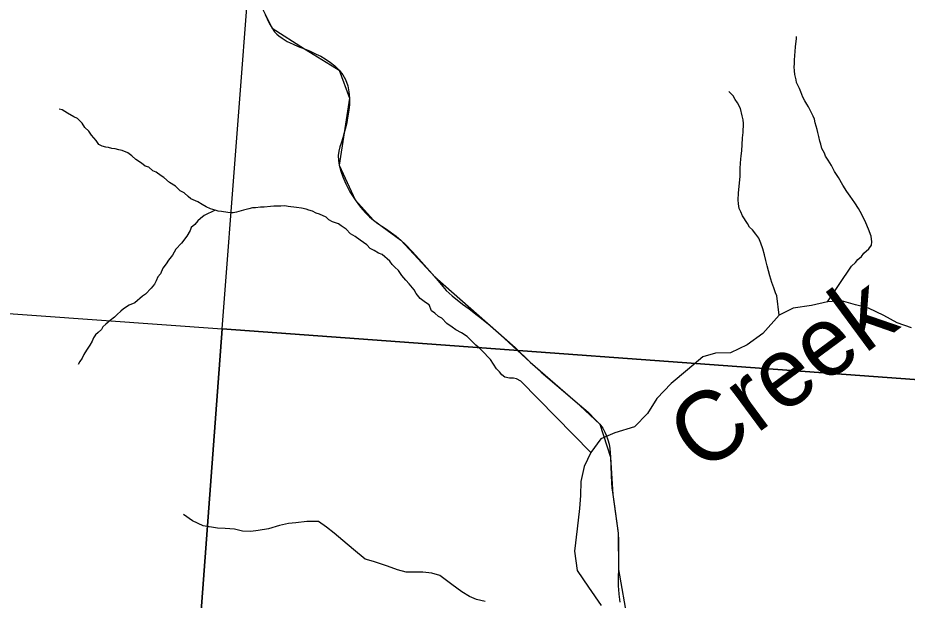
# Model space of a CAD drawing. Extents: x 0 to 82.7, y -0.2 to 22.
# Drawn here: x 6.574 to 7.785, y 18.905 to 19.698 of the extents above; entities that cross this region are included whole.
import ezdxf

# ---------------------------------------------------------------- set-up
doc = ezdxf.new("R2010")
doc.units = 0
for name, color, linetype in [('GM_X_Minor_River', 7, 'Continuous'), ('GM_X_Minor_River_Text', 7, 'Continuous'), ('GM_X_Section', 7, 'Continuous'), ('GM_X_State_Route', 7, 'Continuous'), ('SH_Text', 7, 'Continuous')]:
    doc.layers.add(name, color=color, linetype=linetype)

msp = doc.modelspace()

# ---------------------------------------------------------------- linework, layer by layer
at = {"layer": 'GM_X_Minor_River'}
for points in [[(7.6768, 19.3115), (7.7094, 19.3603), (7.7148, 19.3651), (7.7183, 19.3693), (7.7229, 19.3734), (7.7263, 19.3779), (7.7332, 19.3839), (7.7367, 19.3888), (7.7371, 19.3933), (7.7361, 19.401), (7.7328, 19.4105), (7.7291, 19.4193), (7.7235, 19.4304), (7.7191, 19.4388), (7.7142, 19.4465), (7.7079, 19.4556), (7.703, 19.4618), (7.6978, 19.4702), (7.6918, 19.4806), (7.6862, 19.489), (7.6822, 19.497), (7.6777, 19.5043), (7.6743, 19.51), (7.6725, 19.5139), (7.6692, 19.5204), (7.6677, 19.5261), (7.6662, 19.5303), (7.6652, 19.5364), (7.6637, 19.5421), (7.6626, 19.5459), (7.6615, 19.5508), (7.6601, 19.5554), (7.659, 19.56), (7.6575, 19.5642), (7.6557, 19.568), (7.6508, 19.5768), (7.6486, 19.5807), (7.646, 19.5852), (7.643, 19.5902), (7.6405, 19.5975), (7.6386, 19.6017), (7.6345, 19.6101), (7.6342, 19.6139), (7.6324, 19.6208), (7.6317, 19.6261), (7.6314, 19.6314), (7.6318, 19.6356), (7.6318, 19.6405), (7.6323, 19.6466), (7.6327, 19.6523), (7.6332, 19.6587), (7.6336, 19.6629), (7.6345, 19.6694), (7.6347, 19.6728)], [(7.6111, 19.2933), (7.6077, 19.3197), (7.6058, 19.3236), (7.6036, 19.3308), (7.601, 19.3381), (7.5985, 19.3468), (7.5963, 19.3537), (7.5945, 19.3606), (7.5927, 19.3678), (7.5908, 19.3754), (7.5887, 19.3838), (7.5861, 19.3915), (7.5831, 19.398), (7.5794, 19.4037), (7.5749, 19.4095), (7.5704, 19.4133), (7.5678, 19.4183), (7.5611, 19.4286), (7.5589, 19.434), (7.5567, 19.4386), (7.5556, 19.445), (7.5553, 19.4504), (7.5558, 19.4595), (7.5566, 19.469), (7.5579, 19.4822), (7.5581, 19.4933), (7.5586, 19.5062), (7.5594, 19.51), (7.5602, 19.5176), (7.5607, 19.5251), (7.5612, 19.5346), (7.562, 19.5422), (7.5622, 19.5544), (7.5619, 19.5593), (7.5608, 19.5647), (7.5582, 19.5746), (7.5542, 19.5822), (7.5512, 19.5868), (7.5482, 19.5918), (7.5424, 19.5977)], [(6.7809, 19.4742), (6.773, 19.4807), (6.7692, 19.4831), (6.7624, 19.4881), (6.7583, 19.49), (6.7526, 19.4947), (6.7477, 19.4963), (6.7425, 19.5001), (6.7349, 19.5055), (6.7297, 19.5102), (6.724, 19.5144), (6.7161, 19.5176), (6.7116, 19.5184), (6.7066, 19.5196), (6.7021, 19.5204), (6.6979, 19.5216), (6.6941, 19.522), (6.6889, 19.5236), (6.6847, 19.5259), (6.681, 19.5313), (6.6746, 19.5382), (6.6709, 19.544), (6.6656, 19.549), (6.6619, 19.5547), (6.6555, 19.5609), (6.6506, 19.5632), (6.6419, 19.5683), (6.6348, 19.5729), (6.6306, 19.574)], [(7.3546, 19.1066), (7.2592, 19.2037), (7.2535, 19.2068), (7.2494, 19.2076), (7.2437, 19.2077), (7.2376, 19.2089), (7.2335, 19.212), (7.2301, 19.2162), (7.226, 19.2204), (7.2178, 19.2331), (7.2144, 19.2369), (7.2095, 19.2416), (7.2024, 19.2489), (7.1979, 19.2527), (7.1927, 19.2581), (7.1863, 19.2643), (7.1784, 19.2693), (7.1708, 19.2736), (7.1659, 19.2771), (7.1584, 19.2821), (7.1517, 19.2894), (7.1471, 19.2914), (7.1423, 19.296), (7.1377, 19.2995), (7.1344, 19.3075), (7.1295, 19.3106), (7.122, 19.316), (7.1168, 19.3229), (7.1138, 19.3279), (7.107, 19.3359), (7.1026, 19.3409), (7.0973, 19.3475), (7.0925, 19.354), (7.0876, 19.3586), (7.0842, 19.3624), (7.0808, 19.3667), (7.0703, 19.3759), (7.0654, 19.3779), (7.0594, 19.3814), (7.0541, 19.3841), (7.0496, 19.3891), (7.0406, 19.3953), (7.0334, 19.4007), (7.0274, 19.4042), (7.0214, 19.4104), (7.0146, 19.415), (7.0109, 19.4177), (7.0067, 19.4193), (7.0026, 19.4205), (6.9977, 19.4232), (6.9939, 19.4267), (6.9852, 19.431), (6.9807, 19.4321), (6.9754, 19.4349), (6.9705, 19.4361), (6.9667, 19.4376), (6.9603, 19.4392), (6.9535, 19.4401), (6.9425, 19.4414), (6.9379, 19.4422), (6.9326, 19.4419), (6.9288, 19.4419), (6.9227, 19.4416), (6.9182, 19.4413), (6.9098, 19.4403), (6.9045, 19.4403), (6.8981, 19.4396), (6.8939, 19.4393), (6.8889, 19.4382), (6.8817, 19.4361), (6.8722, 19.4335), (6.8676, 19.4328), (6.8638, 19.4329), (6.8601, 19.4333), (6.8517, 19.4345), (6.8472, 19.435), (6.843, 19.4365), (6.8366, 19.4381), (6.8309, 19.4409), (6.8253, 19.444), (6.8192, 19.4475), (6.8098, 19.4518), (6.806, 19.4549), (6.8008, 19.4599), (6.7955, 19.4626), (6.7888, 19.4688), (6.7809, 19.4742)], [(6.843, 19.4365), (6.8278, 19.4291), (6.8232, 19.425), (6.8193, 19.422), (6.8151, 19.4168), (6.8105, 19.4126), (6.8089, 19.4088), (6.8043, 19.4009), (6.7973, 19.3915), (6.7893, 19.3833), (6.785, 19.3753), (6.7792, 19.3682), (6.7762, 19.3633), (6.7715, 19.3576), (6.7684, 19.3497), (6.7649, 19.3456), (6.7626, 19.3403), (6.7603, 19.3357), (6.7557, 19.3301), (6.748, 19.3222), (6.7438, 19.3192), (6.7334, 19.3102), (6.7258, 19.3069), (6.7182, 19.3021), (6.7143, 19.2987), (6.7097, 19.2942), (6.7059, 19.2908), (6.7001, 19.286), (6.694, 19.2811), (6.6898, 19.2777), (6.6882, 19.274), (6.6836, 19.2698), (6.6798, 19.2665), (6.6775, 19.2627), (6.6755, 19.2582), (6.6721, 19.2525), (6.6678, 19.2457), (6.6639, 19.2397), (6.662, 19.2348), (6.6585, 19.2302), (6.6562, 19.2265)], [(7.7911, 19.2764), (7.7718, 19.2829), (7.7536, 19.2929), (7.7325, 19.3029), (7.7151, 19.3075), (7.6961, 19.3129), (7.6768, 19.3115), (7.6548, 19.3067), (7.6301, 19.303), (7.6111, 19.2933), (7.5889, 19.2683), (7.5672, 19.2529), (7.5447, 19.242), (7.5243, 19.2417), (7.5072, 19.2368), (7.4862, 19.2191), (7.4641, 19.2002), (7.4446, 19.1802), (7.4316, 19.1598), (7.414, 19.1416), (7.3874, 19.1334), (7.368, 19.1252), (7.3546, 19.1066), (7.3454, 19.0873), (7.3411, 19.0672), (7.3405, 19.0482), (7.3393, 19.0304), (7.3361, 19.0027), (7.3325, 18.9723), (7.3361, 18.9461), (7.3515, 18.9232), (7.3687, 18.8981)], [(7.2108, 18.9036), (7.199, 18.9066), (7.1891, 18.9104), (7.1789, 18.9169), (7.1652, 18.9268), (7.1489, 18.939), (7.1382, 18.9424), (7.1257, 18.9435), (7.1029, 18.9436), (7.0911, 18.9466), (7.0778, 18.9516), (7.0683, 18.955), (7.0584, 18.958), (7.0474, 18.9615), (7.0314, 18.9744), (7.0166, 18.9869), (7.0052, 18.9968), (6.9946, 19.0048), (6.9836, 19.0124), (6.968, 19.0128), (6.9528, 19.0109), (6.9429, 19.0098), (6.9307, 19.0072), (6.9155, 19.0026), (6.9015, 19.0003), (6.8916, 18.9992), (6.8802, 18.9996), (6.8691, 19.0023), (6.8566, 19.003), (6.8463, 19.0034), (6.8266, 19.0065), (6.8121, 19.0133), (6.8, 19.0221)]]:
    msp.add_lwpolyline(points, dxfattribs=at)
at = {"layer": 'GM_X_Section'}
for points in [[(6.9306, 20.2917), (7.9492, 20.2127), (7.8698, 19.2002), (6.8524, 19.275)], [(5.8471, 19.3468), (6.8524, 19.275), (6.7772, 18.2637), (5.7783, 18.3279)], [(6.8524, 19.275), (7.8698, 19.2002), (7.7927, 18.1915), (6.7772, 18.2637)]]:
    msp.add_lwpolyline(points, close=True, dxfattribs=at)
at = {"layer": 'GM_X_State_Route'}
msp.add_lwpolyline([(6.9111, 19.7028), (6.9167, 19.6908), (6.9207, 19.6838), (6.9238, 19.6792), (6.9269, 19.6759), (6.9298, 19.6734), (6.9341, 19.6702), (6.9412, 19.6661), (6.9491, 19.6623), (6.9562, 19.6592), (6.9645, 19.6558), (6.9721, 19.6527), (6.9806, 19.6488), (6.987, 19.6457), (6.9927, 19.6422), (7.0001, 19.6371), (7.0061, 19.6326), (7.012, 19.6269), (7.0167, 19.6205), (7.0204, 19.6141), (7.0234, 19.6057), (7.0252, 19.5973), (7.026, 19.5886), (7.0259, 19.5801), (7.0252, 19.5725), (7.0238, 19.5646), (7.0222, 19.5558), (7.0209, 19.5498), (7.0187, 19.5416), (7.017, 19.5347), (7.0144, 19.5277), (7.0125, 19.5223), (7.0115, 19.5166), (7.0104, 19.5106), (7.0107, 19.5037), (7.0118, 19.4977), (7.014, 19.4896), (7.017, 19.4818), (7.0211, 19.4721), (7.0265, 19.4612), (7.0334, 19.4505), (7.0409, 19.4403), (7.0476, 19.4329), (7.0532, 19.4272), (7.0586, 19.4228), (7.0645, 19.4183), (7.0699, 19.4146), (7.0763, 19.4103), (7.0833, 19.4055), (7.0893, 19.4011), (7.0958, 19.3955), (7.102, 19.3897), (7.111, 19.3801), (7.1203, 19.3701), (7.1419, 19.3456), (7.1528, 19.3323), (7.1577, 19.3272), (7.1656, 19.3198), (7.1798, 19.3085), (7.1887, 19.3022), (7.1958, 19.2967), (7.2055, 19.2889), (7.2173, 19.2792), (7.225, 19.2726), (7.2513, 19.2492), (7.2717, 19.2296), (7.2869, 19.2157), (7.3175, 19.1901), (7.3334, 19.1766), (7.3508, 19.1613), (7.361, 19.151), (7.3668, 19.145), (7.3707, 19.1395), (7.3737, 19.1344), (7.3755, 19.1302), (7.3776, 19.1238), (7.3794, 19.1179), (7.3804, 19.112), (7.3812, 19.1001), (7.382, 19.0757), (7.3825, 19.0653), (7.3832, 19.0585), (7.3845, 19.0494), (7.3864, 19.0368), (7.3908, 19.0034), (7.3916, 18.9966), (7.3921, 18.9861), (7.3922, 18.9718), (7.392, 18.9474), (7.3918, 18.9371), (7.3918, 18.9307), (7.3919, 18.9248), (7.392, 18.92), (7.3927, 18.9136), (7.394, 18.903)], dxfattribs=at)
at = {"layer": 'SH_Text'}
for p, q in [((6.904, 19.7178), (6.9207, 19.6838)), ((6.9207, 19.6838), (6.9645, 19.6558)), ((6.9645, 19.6558), (7.012, 19.6269)), ((7.012, 19.6269), (7.026, 19.5886)), ((7.026, 19.5886), (7.0187, 19.5416)), ((7.0187, 19.5416), (7.0118, 19.4977)), ((7.0118, 19.4977), (7.0334, 19.4505)), ((7.0334, 19.4505), (7.0586, 19.4228)), ((7.0586, 19.4228), (7.0958, 19.3955)), ((7.0958, 19.3955), (7.1419, 19.3456)), ((7.1419, 19.3456), (7.225, 19.2726)), ((7.225, 19.2726), (7.2717, 19.2296)), ((7.2717, 19.2296), (7.3334, 19.1766)), ((7.3334, 19.1766), (7.3668, 19.145)), ((7.3668, 19.145), (7.3812, 19.1001)), ((7.3812, 19.1001), (7.3845, 19.0494)), ((7.3845, 19.0494), (7.3916, 18.9966)), ((7.3916, 18.9966), (7.392, 18.9474)), ((7.392, 18.9474), (7.4051, 18.8747))]:
    msp.add_line(p, q, dxfattribs=at)

# ---------------------------------------------------------------- texts
at = {"layer": 'GM_X_Minor_River_Text'}
msp.add_text('Creek', height=0.0947, rotation=36.4689, dxfattribs=at).set_placement((7.5062, 19.0766))

doc.saveas('drawing.dxf')
